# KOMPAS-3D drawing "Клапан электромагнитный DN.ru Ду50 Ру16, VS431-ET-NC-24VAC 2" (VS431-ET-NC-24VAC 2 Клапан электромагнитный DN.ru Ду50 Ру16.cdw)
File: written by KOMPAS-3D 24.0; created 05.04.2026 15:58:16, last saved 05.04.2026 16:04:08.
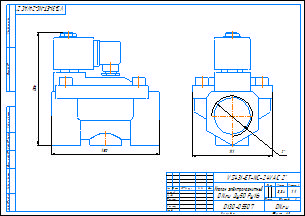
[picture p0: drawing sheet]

Document properties: c3d_UniqueCompID: ef56311e-7521-43dc-8291-0e6108b3d81d; Автор: artio; Класс точности: c; Знак неуказанной шероховатости: Шероховатость не задана; Рассекать на разрезах: Да; c3d_UniqueCompID: ef56311e-7521-43dc-8291-0e6108b3d81d; Автор: artio; Класс точности: c; Знак неуказанной шероховатости: Шероховатость не задана; Рассекать на разрезах: Да; c3d_UniqueCompID: ef56311e-7521-43dc-8291-0e6108b3d81d; Автор: artio; Класс точности: c; Знак неуказанной шероховатости: Шероховатость не задана; Рассекать на разрезах: Да; c3d_UniqueCompID: ef56311e-7521-43dc-8291-0e6108b3d81d; Автор: artio; Класс точности: c; Знак неуказанной шероховатости: Шероховатость не задана; Рассекать на разрезах: Да; c3d_UniqueCompID: ef56311e-7521-43dc-8291-0e6108b3d81d; Автор: artio; Класс точности: c; Знак неуказанной шероховатости: Шероховатость не задана; Рассекать на разрезах: Да; Автор: artio; Форматы листов документа: A3; Полное имя файла: VS431-ET-NC-24VAC 2 Клапан электромагнитный DN.ru Ду50 Ру16.m3d; Масса: 3.341; Наименование: Клапан электромагнитный DN.ru Ду50 Ру16; Количество листов документа: 1; Примечание: D130-05507

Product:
- Body: Тело 1  | qty 1
    Масса: 6.703651
- Part/product: Клапан электромагнитный DN.ru Ду50 Ру16  | designation VS431-ET-NC-24VAC 2
    Масса: 3.341
    Раздел спецификации: Прочие изделия
    Примечание: D130-05507
    additional columns: ef56311e-7521-43dc-8291-0e6108b3d81d; artio; c; Шероховатость не задана; Да

Views: Вид 1, Спереди
Referenced files in C:\Users\artio\OneDrive\Рабочий стол\Клапан электромагнитный DN.ru\VS431\VS431-ET-NC\: VS431-ET-NC-24VAC 3-4 Клапан электромагнитный DN.ru Ду20 Ру16.m3d, VS431-ET-NC-24VAC 2 Клапан электромагнитный DN.ru Ду50 Ру16.m3d, VS431-ET-NC-24VAC 3-4 Клапан электромагнитный DN.ru Ду20 Ру16.cdw
Referenced files in C:\Users\artio\OneDrive\Рабочий стол\Клапан электромагнитный DN.ru\VS431\VS431-ET-NC\VS431-ET-NC-24VAC\Ду50\: VS431-ET-NC-24VAC 2 Клапан электромагнитный DN.ru Ду50 Ру16.m3d
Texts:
  VS431-ET-NC-24VAC 2
  Клапан электромагнитный
  DN.ru Ду50 Ру16
  VS431-ET-NC-24VAC 2"
  VS431-ET-NC-24VAC 2"-
  Клапан электромагнитный DN.ru Ду50 Ру16
  VS431-ET-NC-24VAC 2 Клапан электромагнитный DN.ru Ду50 Ру16
Dimensions and other numbers on the sheet: 0; 3; 2; 4; 111; 1:1; 1; 3,34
